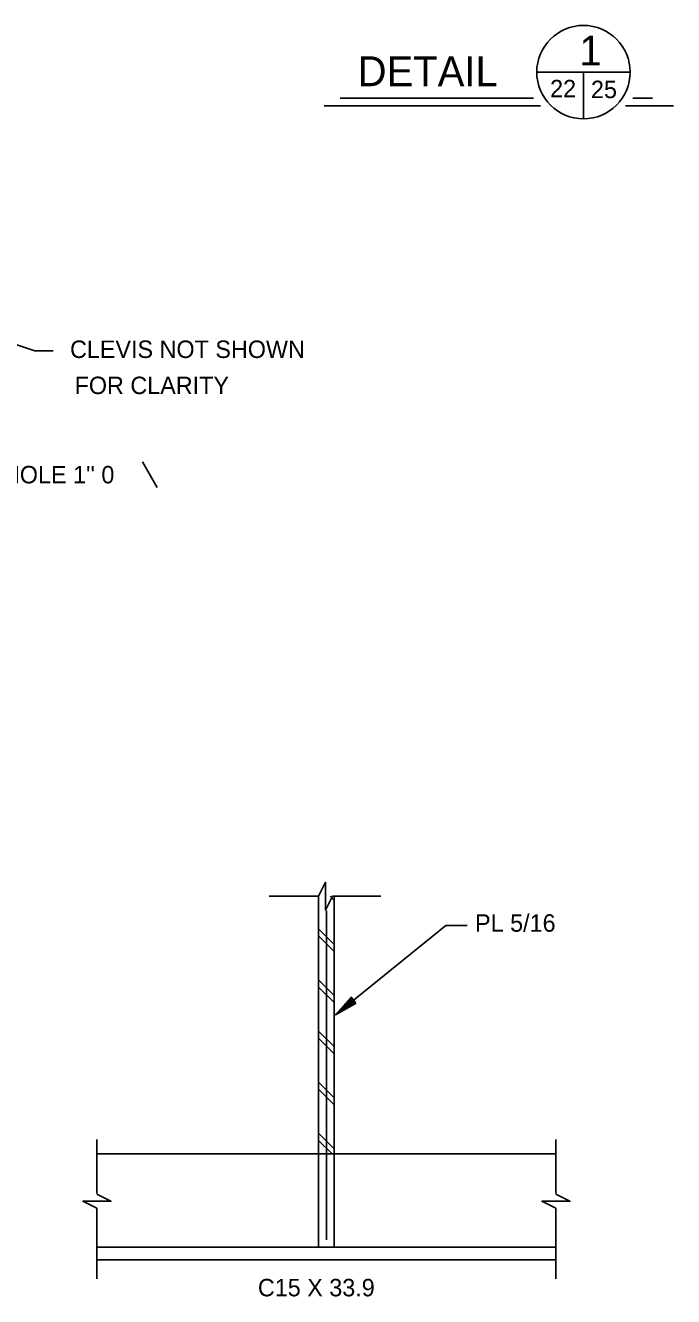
# Model space of a CAD drawing. Extents: x 0.1 to 13.5, y 0.1 to 9.5.
# Drawn here: x 8.688 to 10.422, y 2.849 to 6.249 of the extents above; entities that cross this region are included whole.
import ezdxf

# ---------------------------------------------------------------- set-up
doc = ezdxf.new("R2010")
doc.units = 0
for name, color, linetype in [('Level 1', 7, 'Continuous'), ('Level 13', 7, 'Continuous'), ('Level 25', 7, 'Continuous'), ('Level 3', 7, 'Continuous'), ('Level 44', 7, 'Continuous')]:
    doc.layers.add(name, color=color, linetype=linetype)

msp = doc.modelspace()

# ---------------------------------------------------------------- linework, layer by layer
at = {"layer": 'Level 13'}
for points in [[(9.4725, 3.92), (9.4912, 3.9575), (9.4912, 3.8826), (9.5099, 3.92)], [(8.8795, 3.0856), (8.842, 3.1042), (8.9169, 3.1042), (8.8795, 3.1229)], [(10.1073, 3.0856), (10.0698, 3.1042), (10.1447, 3.1042), (10.1073, 3.1229)]]:
    msp.add_lwpolyline(points, dxfattribs=at)
at = {"layer": 'Level 25'}
for p, q in [((9.0012, 5.0822), (9.0407, 5.0138)), ((9.4725, 3.92), (9.3403, 3.92)), ((9.4725, 3.2311), (9.4725, 3.92)), ((9.5142, 3.2311), (9.5142, 3.92)), ((9.4934, 3.0007), (9.4934, 3.8809)), ((8.8795, 3.1245), (8.8795, 3.2694)), ((10.1073, 3.1245), (10.1073, 3.2694)), ((10.1073, 3.2311), (8.8795, 3.2311)), ((9.4725, 2.9811), (9.4725, 3.2311)), ((9.5142, 2.9811), (9.5142, 3.2311)), ((8.8795, 2.8962), (8.8795, 3.0856)), ((10.1073, 2.8962), (10.1073, 3.0856)), ((10.1073, 2.9811), (8.8795, 2.9811)), ((10.1073, 2.9478), (8.8795, 2.9478))]:
    msp.add_line(p, q, dxfattribs=at)
at = {"layer": 'Level 3'}
for p, q in [((10.3058, 6.1245), (10.0558, 6.1245)), ((10.1808, 6.1245), (10.1808, 5.9995)), ((10.0473, 6.0549), (9.5303, 6.0549)), ((10.3655, 6.0549), (10.3125, 6.0549)), ((10.0657, 6.0341), (9.4873, 6.0341)), ((10.4218, 6.0341), (10.2931, 6.0341)), ((9.5099, 3.92), (9.6387, 3.92)), ((9.531, 3.6138), (9.531, 3.6138)), ((9.5175, 3.603), (9.5175, 3.603))]:
    msp.add_line(p, q, dxfattribs=at)
for points in [[(8.763, 5.3793), (8.7133, 5.3793), (7.9873, 5.6204)], [(9.8702, 3.8416), (9.8131, 3.8416), (9.5175, 3.603)], [(9.5725, 3.6341), (9.5175, 3.603), (9.5595, 3.6502), (9.5706, 3.6364), (9.531, 3.6138), (9.5595, 3.6459), (9.5666, 3.6371), (9.5439, 3.6243), (9.5595, 3.6416), (9.5625, 3.638), (9.5574, 3.6352)]]:
    msp.add_lwpolyline(points, dxfattribs=at)
msp.add_circle((10.1808, 6.1245), 0.125, dxfattribs=at)
at = {"layer": 'Level 44'}
for p, q in [((9.5142, 3.9089), (9.5031, 3.92)), ((9.5142, 3.7911), (9.4725, 3.8328)), ((9.5142, 3.7722), (9.4725, 3.8139)), ((9.5142, 3.6544), (9.4725, 3.6961)), ((9.5142, 3.6355), (9.4725, 3.6772)), ((9.5142, 3.5177), (9.4725, 3.5593)), ((9.5142, 3.4988), (9.4725, 3.5405)), ((9.5142, 3.381), (9.4725, 3.4226)), ((9.5142, 3.3621), (9.4725, 3.4038)), ((9.5142, 3.2443), (9.4725, 3.2859)), ((9.5085, 3.2311), (9.4725, 3.2671))]:
    msp.add_line(p, q, dxfattribs=at)

# ---------------------------------------------------------------- texts
at = {"layer": 'Level 1'}
msp.add_text('C15 X 33.9', height=0.0467, dxfattribs=at).set_placement((9.3101, 2.8498))
at = {"layer": 'Level 25'}
for s, height, p in [('CLEVIS NOT SHOWN', 0.046698, (8.8077, 5.3599)), ('FOR CLARITY', 0.046698, (8.8199, 5.2633)), ("DRAIN HOLE 1'' 0", 0.046698, (8.4166, 5.0245)), ('PL 5/16', 0.0467, (9.8909, 3.8251))]:
    msp.add_text(s, height=height, dxfattribs=at).set_placement(p)
at = {"layer": 'Level 3'}
for s, height, p in [('1', 0.08, (10.1699, 6.1423)), ('DETAIL', 0.08, (9.577, 6.0869)), ('22', 0.04679, (10.0915, 6.0571)), ('25', 0.04679, (10.2008, 6.0549))]:
    msp.add_text(s, height=height, dxfattribs=at).set_placement(p)

doc.saveas('drawing.dxf')
